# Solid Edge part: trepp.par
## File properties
Author: Indrek
Template: Normal.par
Last saved by: Indrek
Revision: 2
Application: Solid Edge
Accuracy: 0,990
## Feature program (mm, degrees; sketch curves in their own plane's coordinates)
sketch for "unnamed Protrusion 1" plane through (0, 0, 0) normal (1, 0, 0) x-axis (0, 1, 0)
  line (-21, 24) -> (-24, 24)
  line (-24, 24) -> (-24, 27)
  line (-24, 27) -> (-27, 27)
  line (-27, 27) -> (-27, 30)
  line (-27, 30) -> (-30, 30)
  line (-30, 30) -> (-30, 33)
  line (-30, 33) -> (-33, 33)
  line (-33, 33) -> (-33, 36)
  line (-33, 36) -> (-36, 36)
  line (-36, 36) -> (-36, 30)
  line (-36, 30) -> (-6, 0)
  line (-6, 0) -> (0, 0)
  line (0, 0) -> (0, 3)
  line (0, 3) -> (-3, 3)
  line (-3, 3) -> (-3, 6)
  line (-3, 6) -> (-6, 6)
  line (-6, 6) -> (-6, 9)
  line (-6, 9) -> (-9, 9)
  line (-9, 9) -> (-9, 12)
  line (-9, 12) -> (-12, 12)
  line (-12, 12) -> (-12, 15)
  line (-12, 15) -> (-15, 15)
  line (-15, 15) -> (-15, 18)
  line (-15, 18) -> (-18, 18)
  line (-18, 18) -> (-18, 21)
  line (-18, 21) -> (-21, 21)
  line (-21, 21) -> (-21, 24)
extrude "unnamed Protrusion 1" add finite 20 along +normal
swept protrusion "unnamed SweptProtrusion 1"
swept protrusion "unnamed SweptProtrusion 2"
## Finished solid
Body 1: solid body, 44 faces, 172 edges, 114 vertices.
  Faces by surface: plane 42, spline 2
  Edges by curve: line 110, intersection 58, ellipse 4
Bounding box of the edges (mm; curved faces can reach further): 20.898 x 36.000 x 47.096, from (-0.4489, -36, 0) to (20.4489, 0, 47.0961).
Planar faces by outward normal: +x 1, +y 18, +z 18, -x 1, -y 2, -z 1, oblique 1
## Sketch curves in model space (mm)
line (20, -36, 36) -> (20, 0, 0.113)
ellipse centre (19.9201, 0, 5.5728) radii 5.5232, 0.5287
ellipse centre (0.0799, 0, 5.5728) radii 5.5232, 0.5287
line (10, 0, 0) -> (10, 0, 15.2709)
line (0, 0, 0) -> (0, -36, 36)
line (0, 0, 3) -> (0, -3, 3)
line (0, -3, 3) -> (0, -3, 6)
line (0, -3, 6) -> (0, -6, 6)
line (0, -6, 6) -> (0, -6, 9)
line (0, -6, 9) -> (0, -9, 9)
line (0, -9, 9) -> (0, -9, 12)
line (0, -9, 12) -> (0, -12, 12)
line (0, -12, 12) -> (0, -12, 15)
line (0, -12, 15) -> (0, -15, 15)
line (0, -15, 15) -> (0, -15, 18)
line (0, -15, 18) -> (0, -18, 18)
line (0, -18, 18) -> (0, -18, 21)
line (0, -18, 21) -> (0, -21, 21)
line (0, -21, 21) -> (0, -21, 24)
line (0, -21, 24) -> (0, -24, 24)
line (0, -24, 24) -> (0, -24, 27)
line (0, -24, 27) -> (0, -27, 27)
line (0, -27, 27) -> (0, -27, 30)
line (0, -27, 30) -> (0, -30, 30)
line (0, -30, 30) -> (0, -30, 33)
line (0, -30, 33) -> (0, -33, 33)
line (0, -33, 33) -> (0, -33, 36)
line (0, -33, 36) -> (0, -36, 36)
line (0, -36, 36) -> (0, -36, 30)
line (0, -36, 30) -> (0, -6, 0)
line (0, -6, 0) -> (0, 0, 0)
line (0, 0, 0) -> (0, 0, 3)
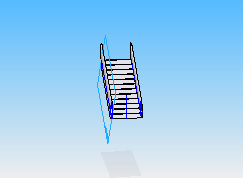
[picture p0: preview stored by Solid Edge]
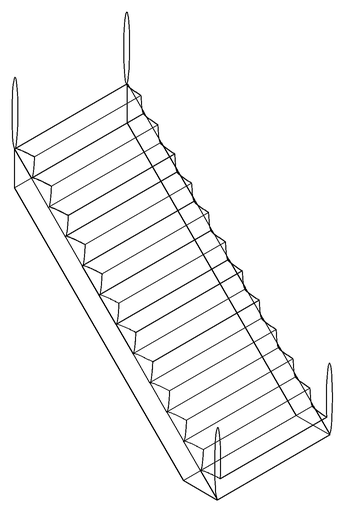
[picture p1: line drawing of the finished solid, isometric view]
